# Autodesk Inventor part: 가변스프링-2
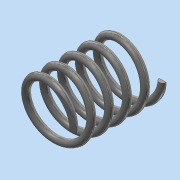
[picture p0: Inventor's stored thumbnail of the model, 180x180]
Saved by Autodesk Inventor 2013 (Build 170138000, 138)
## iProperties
Created: 2018-10
Part Number: 가변스프링-2
Material: 스테인레스 스틸
Document SubType Name: Modeling
Designer: Administrator
Density: 8.08 g/cm^3
Mass: 6.2701 g
Surface Area: 15.7676 cm^2
Volume: 0.776002 cm^3
Author: Administrator
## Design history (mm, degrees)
sketch "스케치1"
  geometry: L1 (0, 0)-(0, 25.572); L2 (0, 0)-(8, 0); L3 (0, 25.572)-(8, 25.572); C1 r 1 at (8, 0)
  constraints: 6 end point, 1 centre point, 1 coincident, 1 parallel, 1 perpendicular, 1 vertical
  dimensions: "d0" = 25.57164 distance of L1.start L1.end (derived); "d1" = 8 distance of L1.start L2.end; "d2" = 8 distance of L1.end L3.end; "d3" = 2 diameter of C1
feature "코일1" sketch "스케치1" pitch "d4" = 10; turns "d6" = 5; dims "d5" = 25.57164 (= d0), "d7" = 0, angle "d8" = 90 deg, angle "d9" = 90 deg, "d10" = 0, "d11" = 0
sketch "스케치2"
  geometry: L1 (25.572, 11.5)-(0, 11.5); L2 (0, 11.5)-(0, -11.5); L3 (0, -11.5)-(25.572, -11.5); L4 (25.572, -11.5)-(25.572, 11.5); 2 further points
  constraints: 8 end point, 2 parallel, 1 coincident, 1 horizontal, 1 midpoint, 1 perpendicular
  dimensions: "d12" = 25.57164 distance between parallel lines of L2 L4 (derived); "d14" = 23 distance between parallel lines of L1 L3
extrude "돌출1" sketch "스케치2" stored distance "d15" = 0; taper "d16" = 0 deg
node "솔리드1"
